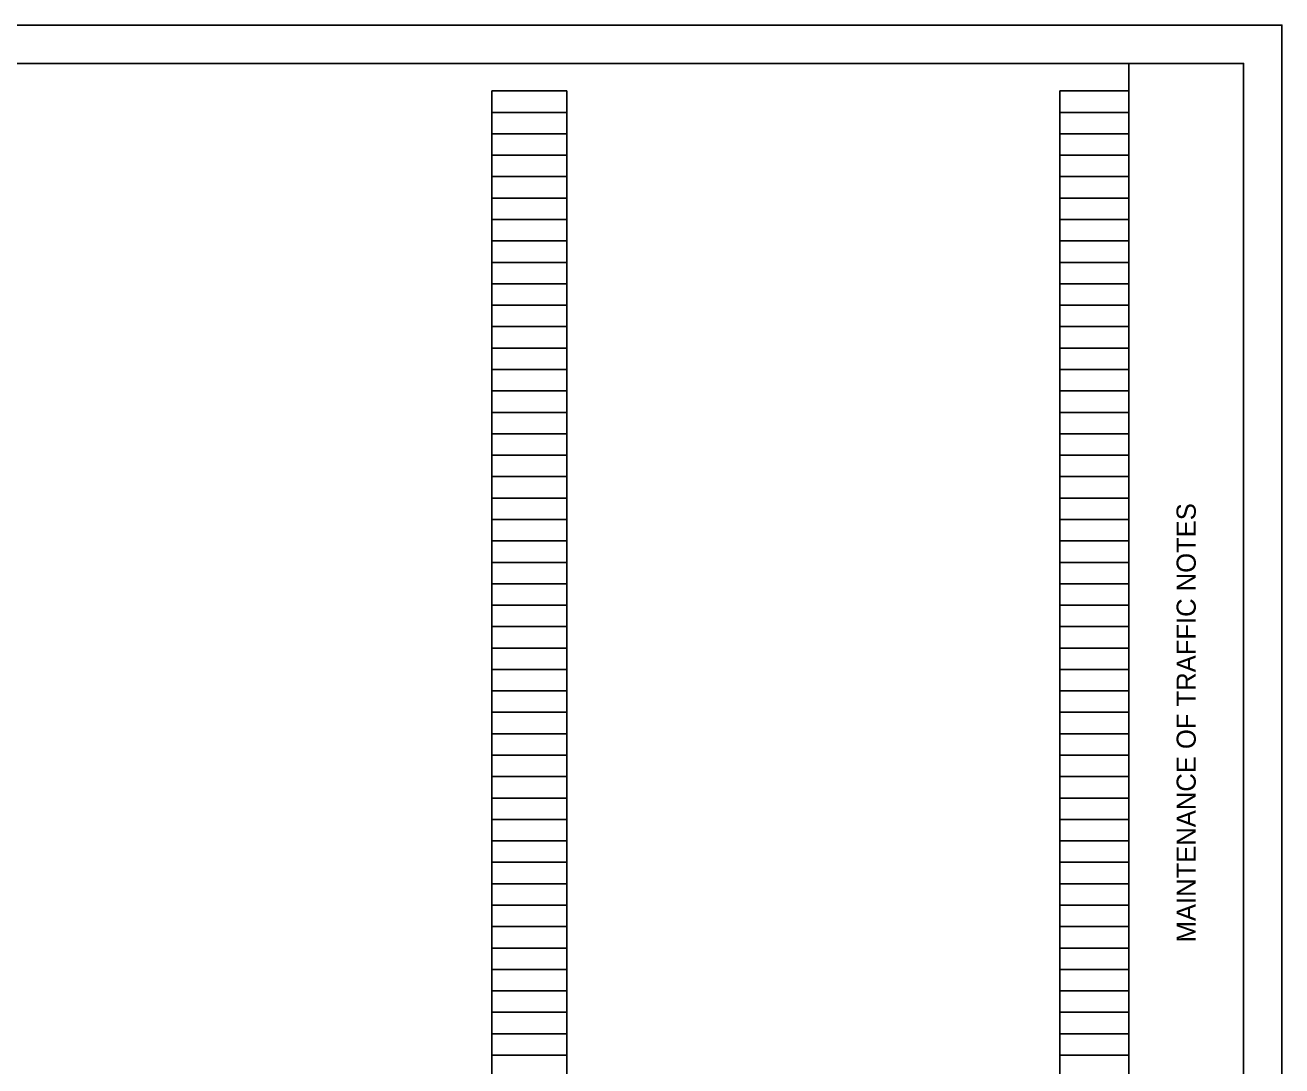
# Model space of a CAD drawing. Extents: x 0 to 34.1, y -5.4 to 22.
# Drawn here: x 17.58 to 34, y 8.4 to 22 of the extents above; entities that cross this region are included whole.
import ezdxf

# ---------------------------------------------------------------- set-up
doc = ezdxf.new("R2010")
doc.units = 0
for name, color, linetype in [('SH_Border', 7, 'Continuous'), ('SH_Cut_Line', 7, 'Continuous'), ('SH_Data', 7, 'Continuous')]:
    doc.layers.add(name, color=color, linetype=linetype)

msp = doc.modelspace()

# ---------------------------------------------------------------- linework, layer by layer
at = {"layer": 'SH_Border'}
msp.add_line((32, 0.5), (32, 21.5), dxfattribs=at)
msp.add_lwpolyline([(1.5, 21.5), (33.5, 21.5), (33.5, 0.5), (1.5, 0.5)], close=True, dxfattribs=at)
at = {"layer": 'SH_Cut_Line'}
msp.add_lwpolyline([(0, 0), (34, 0), (34, 22), (0, 22)], close=True, dxfattribs=at)
at = {"layer": 'SH_Data'}
for p, q in [((23.68, 0.98), (23.68, 21.14)), ((23.68, 21.14), (24.66, 21.14)), ((24.66, 0.98), (24.66, 21.14)), ((31.1, 0.98), (31.1, 21.14)), ((31.1, 21.14), (32, 21.14)), ((32, 0.98), (32, 21.14)), ((23.68, 20.86), (24.66, 20.86)), ((31.1, 20.86), (32, 20.86)), ((23.68, 20.58), (24.66, 20.58)), ((31.1, 20.58), (32, 20.58)), ((23.68, 20.3), (24.66, 20.3)), ((31.1, 20.3), (32, 20.3)), ((23.68, 20.02), (24.66, 20.02)), ((31.1, 20.02), (32, 20.02)), ((23.68, 19.74), (24.66, 19.74)), ((31.1, 19.74), (32, 19.74)), ((23.68, 19.46), (24.66, 19.46)), ((31.1, 19.46), (32, 19.46)), ((23.68, 19.18), (24.66, 19.18)), ((31.1, 19.18), (32, 19.18)), ((23.68, 18.9), (24.66, 18.9)), ((31.1, 18.9), (32, 18.9)), ((23.68, 18.62), (24.66, 18.62)), ((31.1, 18.62), (32, 18.62)), ((23.68, 18.34), (24.66, 18.34)), ((31.1, 18.34), (32, 18.34)), ((23.68, 18.06), (24.66, 18.06)), ((31.1, 18.06), (32, 18.06)), ((23.68, 17.78), (24.66, 17.78)), ((31.1, 17.78), (32, 17.78)), ((23.68, 17.5), (24.66, 17.5)), ((31.1, 17.5), (32, 17.5)), ((23.68, 17.22), (24.66, 17.22)), ((31.1, 17.22), (32, 17.22)), ((23.68, 16.94), (24.66, 16.94)), ((31.1, 16.94), (32, 16.94)), ((23.68, 16.66), (24.66, 16.66)), ((31.1, 16.66), (32, 16.66)), ((23.68, 16.38), (24.66, 16.38)), ((31.1, 16.38), (32, 16.38)), ((23.68, 16.1), (24.66, 16.1)), ((31.1, 16.1), (32, 16.1)), ((23.68, 15.82), (24.66, 15.82)), ((31.1, 15.82), (32, 15.82)), ((23.68, 15.54), (24.66, 15.54)), ((31.1, 15.54), (32, 15.54)), ((23.68, 15.26), (24.66, 15.26)), ((31.1, 15.26), (32, 15.26)), ((23.68, 14.98), (24.66, 14.98)), ((31.1, 14.98), (32, 14.98)), ((23.68, 14.7), (24.66, 14.7)), ((31.1, 14.7), (32, 14.7)), ((23.68, 14.42), (24.66, 14.42)), ((31.1, 14.42), (32, 14.42)), ((23.68, 14.14), (24.66, 14.14)), ((31.1, 14.14), (32, 14.14)), ((23.68, 13.86), (24.66, 13.86)), ((31.1, 13.86), (32, 13.86)), ((23.68, 13.58), (24.66, 13.58)), ((31.1, 13.58), (32, 13.58)), ((23.68, 13.3), (24.66, 13.3)), ((31.1, 13.3), (32, 13.3)), ((23.68, 13.02), (24.66, 13.02)), ((31.1, 13.02), (32, 13.02)), ((23.68, 12.74), (24.66, 12.74)), ((31.1, 12.74), (32, 12.74)), ((23.68, 12.46), (24.66, 12.46)), ((31.1, 12.46), (32, 12.46)), ((23.68, 12.18), (24.66, 12.18)), ((31.1, 12.18), (32, 12.18)), ((23.68, 11.9), (24.66, 11.9)), ((31.1, 11.9), (32, 11.9)), ((23.68, 11.62), (24.66, 11.62)), ((31.1, 11.62), (32, 11.62)), ((23.68, 11.34), (24.66, 11.34)), ((31.1, 11.34), (32, 11.34)), ((23.68, 11.06), (24.66, 11.06)), ((31.1, 11.06), (32, 11.06)), ((23.68, 10.78), (24.66, 10.78)), ((31.1, 10.78), (32, 10.78)), ((23.68, 10.5), (24.66, 10.5)), ((31.1, 10.5), (32, 10.5)), ((23.68, 10.22), (24.66, 10.22)), ((31.1, 10.22), (32, 10.22)), ((23.68, 9.94), (24.66, 9.94)), ((31.1, 9.94), (32, 9.94)), ((23.68, 9.66), (24.66, 9.66)), ((31.1, 9.66), (32, 9.66)), ((23.68, 9.38), (24.66, 9.38)), ((31.1, 9.38), (32, 9.38)), ((23.68, 9.1), (24.66, 9.1)), ((31.1, 9.1), (32, 9.1)), ((23.68, 8.82), (24.66, 8.82)), ((31.1, 8.82), (32, 8.82)), ((23.68, 8.54), (24.66, 8.54)), ((31.1, 8.54), (32, 8.54))]:
    msp.add_line(p, q, dxfattribs=at)

# ---------------------------------------------------------------- texts
msp.add_text('MAINTENANCE OF TRAFFIC NOTES', height=0.25, rotation=90, dxfattribs=at).set_placement((32.875, 10.014))

doc.saveas('drawing.dxf')
